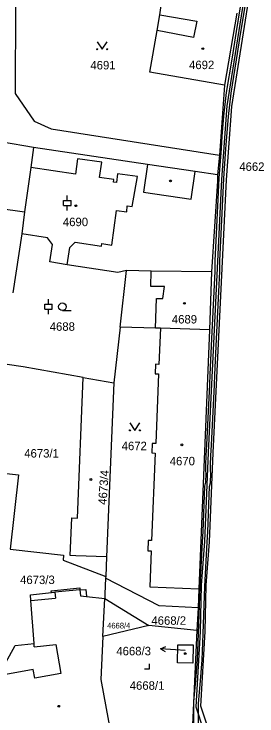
# Model space of a CAD drawing. Extents: x -756746 to -753363, y -1166406 to -1161727.
# Drawn here: x -755427.8 to -755379, y -1166083.9 to -1165943 of the extents above; entities that cross this region are included whole.
import ezdxf

# ---------------------------------------------------------------- set-up
doc = ezdxf.new("R2010")
doc.units = 0
for name, color, linetype in [('Hranice parcel', 7, 'Continuous'), ('Parcelní čísla', 7, 'Continuous'), ('Pop  PČ popisy', 7, 'Continuous'), ('Vnitřní kresba', 7, 'Continuous'), ('Věcná břemena k části', 7, 'Continuous'), ('Značky budov', 7, 'Continuous'), ('Značky kultur', 7, 'Continuous')]:
    doc.layers.add(name, color=color, linetype=linetype)

msp = doc.modelspace()

# ---------------------------------------------------------------- linework, layer by layer
at = {"layer": 'Hranice parcel'}
for p, q in [((-755383.06, -1165942.82), (-755385.55, -1165957.23)), ((-755385.55, -1165957.23), (-755386.57, -1165971.34)), ((-755423.88, -1165969.75), (-755430.07, -1165968.71)), ((-755386.57, -1165971.34), (-755386.95, -1165975.24)), ((-755425.63, -1165982.68), (-755426.22, -1165987.11)), ((-755426.22, -1165987.11), (-755428, -1165998.93)), ((-755406.47, -1166005.8), (-755405.17, -1165994.49)), ((-755388.17, -1165994.71), (-755388.54, -1166006.37)), ((-755406.47, -1166005.8), (-755407.75, -1166016.98)), ((-755388.54, -1166006.37), (-755398.39, -1166006.06)), ((-755388.54, -1166006.37), (-755390.72, -1166058.33)), ((-755413.89, -1166015.93), (-755407.75, -1166016.98)), ((-755407.75, -1166016.98), (-755409.19, -1166051.95)), ((-755409.19, -1166051.95), (-755409.37, -1166055.84)), ((-755409.37, -1166055.84), (-755409.38, -1166056.19)), ((-755390.72, -1166058.33), (-755390.85, -1166062.19)), ((-755413.21, -1166059.89), (-755409.57, -1166060.26)), ((-755409.94, -1166067.89), (-755409.57, -1166060.26)), ((-755409.57, -1166060.26), (-755400.71, -1166065.73)), ((-755390.85, -1166062.19), (-755391.06, -1166066.74)), ((-755400.71, -1166065.73), (-755409.94, -1166067.89)), ((-755391.06, -1166066.74), (-755400.71, -1166065.73)), ((-755391.06, -1166066.74), (-755392.01, -1166087.13))]:
    msp.add_line(p, q, dxfattribs=at)
for points in [[(-755426.57, -1165935.77), (-755427.46, -1165941.26), (-755427.51, -1165958.93), (-755423.7, -1165964.51), (-755420.3, -1165966.01), (-755386.57, -1165971.34)], [(-755385.55, -1165957.23), (-755400.55, -1165954.63), (-755399.02, -1165946.28), (-755398.52, -1165943.15), (-755398.08, -1165940.42)], [(-755423.88, -1165969.75), (-755424.42, -1165973.76), (-755425.63, -1165982.68)], [(-755386.95, -1165975.24), (-755391.4, -1165974.6), (-755401, -1165973.17), (-755423.88, -1165969.75)], [(-755386.95, -1165975.24), (-755386.95, -1165976.54), (-755388.17, -1165994.71)], [(-755460.03, -1165978.15), (-755458.54, -1165978.33), (-755440.43, -1165980.63), (-755425.63, -1165982.68)], [(-755405.17, -1165994.49), (-755406.91, -1165994.88), (-755417.08, -1165993.3), (-755420.56, -1165992.75), (-755420.01, -1165989.22), (-755421.05, -1165987.91), (-755426.22, -1165987.11)], [(-755388.17, -1165994.71), (-755400.27, -1165994.56), (-755405.17, -1165994.49)], [(-755398.39, -1166006.06), (-755399.35, -1166006.03), (-755406.47, -1166005.8)], [(-755398.39, -1166006.06), (-755398.69, -1166013.3), (-755399.39, -1166013.27), (-755399.47, -1166015.17), (-755398.77, -1166015.2), (-755399.34, -1166029.19), (-755400.03, -1166029.16), (-755400.11, -1166031.06), (-755399.42, -1166031.09), (-755400.15, -1166048.67), (-755400.85, -1166048.65), (-755400.93, -1166050.69), (-755400.23, -1166050.72), (-755400.53, -1166057.92), (-755390.72, -1166058.33)], [(-755413.89, -1166015.93), (-755425.95, -1166013.78), (-755429.15, -1166013.33)], [(-755409.19, -1166051.95), (-755415.36, -1166051.7), (-755416.5, -1166051.65), (-755416.19, -1166044.09), (-755415.05, -1166044.14), (-755413.89, -1166015.93)], [(-755431.68, -1166034.91), (-755426.85, -1166035.45), (-755428.52, -1166050.41)], [(-755428.52, -1166050.41), (-755417.85, -1166051.6), (-755417.89, -1166052.59), (-755409.37, -1166055.84)], [(-755409.38, -1166056.19), (-755409.53, -1166059.33), (-755409.57, -1166060.26)], [(-755390.85, -1166062.19), (-755398.64, -1166061.74), (-755409.38, -1166056.19)], [(-755430.92, -1166075.8), (-755427.55, -1166069.72), (-755423.74, -1166069.35), (-755424.37, -1166060.72), (-755424.46, -1166059.53), (-755420.25, -1166059.11), (-755420.29, -1166058.73), (-755414.57, -1166058.16), (-755414.53, -1166058.58), (-755413.34, -1166058.47), (-755413.21, -1166059.89)], [(-755409.94, -1166067.89), (-755410.35, -1166076.55), (-755407.85, -1166090.02)], [(-755391.8, -1166069.61), (-755391.86, -1166073.26), (-755394.95, -1166073.2), (-755394.93, -1166069.56), (-755391.8, -1166069.61)]]:
    msp.add_lwpolyline(points, dxfattribs=at)
at = {"layer": 'Pop  PČ popisy'}
for p, q in [((-755398.37, -1166070.37), (-755397.34, -1166069.94)), ((-755395.38, -1166070.58), (-755398.37, -1166070.37)), ((-755398.37, -1166070.37), (-755397.41, -1166070.94)), ((-755393.43, -1166070.73), (-755395.38, -1166070.58))]:
    msp.add_line(p, q, dxfattribs=at)
at = {"layer": 'Vnitřní kresba'}
for p, q in [((-755398.52, -1165943.15), (-755391.11, -1165944.41)), ((-755391.11, -1165944.41), (-755391.73, -1165947.67)), ((-755391.73, -1165947.67), (-755399.02, -1165946.28)), ((-755415.01, -1165972.02), (-755415.46, -1165975.09)), ((-755410.17, -1165972.74), (-755415.01, -1165972.02)), ((-755415.46, -1165975.09), (-755424.42, -1165973.76)), ((-755410.62, -1165975.8), (-755410.17, -1165972.74)), ((-755401, -1165973.17), (-755401.82, -1165978.71)), ((-755407.02, -1165975.06), (-755407.17, -1165976.81)), ((-755403.02, -1165975.59), (-755407.02, -1165975.06)), ((-755392.23, -1165980.14), (-755391.4, -1165974.6)), ((-755407.76, -1165976.22), (-755410.62, -1165975.8)), ((-755407.82, -1165976.72), (-755407.76, -1165976.22)), ((-755404.05, -1165981.6), (-755403.02, -1165975.59)), ((-755407.17, -1165976.81), (-755407.82, -1165976.72)), ((-755401.82, -1165978.71), (-755392.23, -1165980.14)), ((-755405.15, -1165982.71), (-755405.05, -1165981.46)), ((-755405.05, -1165981.46), (-755404.05, -1165981.6)), ((-755408.12, -1165989.38), (-755407.19, -1165982.44)), ((-755407.19, -1165982.44), (-755405.15, -1165982.71)), ((-755416.54, -1165989.87), (-755415.49, -1165988.76)), ((-755415.49, -1165988.76), (-755410.21, -1165989.57)), ((-755410.21, -1165989.57), (-755410.14, -1165989.07)), ((-755410.14, -1165989.07), (-755408.12, -1165989.38)), ((-755417.08, -1165993.3), (-755416.54, -1165989.87)), ((-755400.31, -1165997.66), (-755400.27, -1165994.56)), ((-755397.56, -1165997.69), (-755400.31, -1165997.66)), ((-755397.9, -1166000.1), (-755397.56, -1165997.69)), ((-755399.35, -1166006.03), (-755399.16, -1166000.06)), ((-755399.16, -1166000.06), (-755397.9, -1166000.1)), ((-755420.25, -1166059.11), (-755419.57, -1166059.04)), ((-755414.53, -1166058.58), (-755419.57, -1166059.04)), ((-755419.57, -1166059.04), (-755419.47, -1166060.24)), ((-755414.53, -1166058.58), (-755414.41, -1166059.77)), ((-755424.37, -1166060.72), (-755419.47, -1166060.24)), ((-755414.41, -1166059.77), (-755413.21, -1166059.89)), ((-755423.69, -1166069.96), (-755423.74, -1166069.35)), ((-755423.69, -1166069.96), (-755419.38, -1166069.53)), ((-755419.38, -1166069.53), (-755418.36, -1166075.36)), ((-755423.92, -1166074.54), (-755430.92, -1166075.8)), ((-755423.61, -1166076.29), (-755423.92, -1166074.54)), ((-755418.36, -1166075.36), (-755423.61, -1166076.29))]:
    msp.add_line(p, q, dxfattribs=at)
at = {"layer": 'Věcná břemena k části'}
for points in [[(-755385.7, -1165976), (-755385.24, -1165970.06), (-755385.09, -1165967.62), (-755384.74, -1165963.55), (-755384.22, -1165958.86), (-755383.1, -1165952.19), (-755382.24, -1165946.62), (-755380.28, -1165934.63), (-755379.25, -1165927.68), (-755378.78, -1165925.92), (-755378.82, -1165925), (-755376.67, -1165911.82), (-755376.32, -1165909.89), (-755375.93, -1165907.57), (-755373.96, -1165897.48), (-755373.19, -1165893.41), (-755373.15, -1165892.92), (-755371.85, -1165886.32), (-755371.15, -1165882.8), (-755369.79, -1165876), (-755369.69, -1165875.3), (-755368.15, -1165864.9), (-755367.31, -1165860.7)], [(-755373.13, -1165886.12), (-755385.09, -1165961.43), (-755386.11, -1165976.2), (-755388.84, -1166030.96), (-755389.57, -1166048.84), (-755390.21, -1166057.59), (-755390.43, -1166066.89), (-755391.29, -1166082.01), (-755389.73, -1166086.72), (-755384.8, -1166101.6), (-755324.15, -1166091.45)], [(-755324.31, -1166090.47), (-755384.12, -1166100.48), (-755388.74, -1166086.54), (-755390.29, -1166081.87), (-755389.43, -1166066.91), (-755389.21, -1166057.59), (-755388.57, -1166048.9), (-755387.84, -1166031.02), (-755385.11, -1165976.24), (-755384.09, -1165961.55), (-755372.14, -1165886.27)], [(-755381.26, -1165934.47), (-755383.22, -1165946.46), (-755384.08, -1165952.03), (-755385.2, -1165958.72), (-755385.74, -1165963.45), (-755386.09, -1165967.54), (-755386.24, -1165969.99), (-755386.7, -1165975.94), (-755387.24, -1165987.07), (-755387.45, -1165992.53), (-755387.49, -1165994.61), (-755387.62, -1165997.31), (-755388.12, -1166008.18), (-755388.51, -1166015.35), (-755388.55, -1166017.35), (-755389.17, -1166029.45), (-755389.29, -1166031.56), (-755389.32, -1166033.49), (-755389.35, -1166034.64), (-755389.25, -1166035.18), (-755389.38, -1166036.96), (-755389.54, -1166037.72), (-755389.89, -1166046.85), (-755390.04, -1166048.92), (-755390.49, -1166057.87), (-755390.83, -1166067.31), (-755391.04, -1166072.51), (-755391.36, -1166076.71), (-755391.73, -1166081.04), (-755391.75, -1166081.53), (-755391.74, -1166087.08)], [(-755390.73, -1166086.9), (-755390.75, -1166081.36), (-755390.36, -1166076.79), (-755390.04, -1166072.57), (-755389.83, -1166067.35), (-755389.49, -1166057.91), (-755389.04, -1166048.98), (-755388.89, -1166046.91), (-755388.54, -1166037.84), (-755388.38, -1166037.1), (-755388.25, -1166035.14), (-755388.35, -1166034.56), (-755388.32, -1166033.51), (-755388.29, -1166031.6), (-755388.17, -1166029.51), (-755387.55, -1166017.39), (-755387.51, -1166015.39), (-755387.12, -1166008.24), (-755386.62, -1165997.35), (-755386.49, -1165994.65), (-755386.45, -1165992.55), (-755386.24, -1165987.11), (-755385.7, -1165976)]]:
    msp.add_lwpolyline(points, dxfattribs=at)
at = {"layer": 'Značky budov'}
for centre in [(-755389.88, -1165949.94), (-755396.37, -1165976.47), (-755415.36, -1165981.46), (-755393.58, -1166001.05), (-755394.08, -1166029.45), (-755412.34, -1166036.4), (-755393.41, -1166071.34), (-755418.78, -1166081.91)]:
    msp.add_circle(centre, 0.175, dxfattribs=at)
at = {"layer": 'Značky kultur'}
for p, q in [((-755417.07, -1165980.39), (-755417.07, -1165979.39)), ((-755417.82, -1165980.39), (-755416.32, -1165980.39)), ((-755417.82, -1165981.39), (-755417.82, -1165980.39)), ((-755416.32, -1165981.39), (-755416.32, -1165980.39)), ((-755417.82, -1165981.39), (-755416.32, -1165981.39)), ((-755417.07, -1165982.39), (-755417.07, -1165981.39)), ((-755420.85, -1166001.24), (-755420.85, -1166000.24)), ((-755421.6, -1166001.24), (-755420.1, -1166001.24)), ((-755421.6, -1166002.24), (-755421.6, -1166001.24)), ((-755420.1, -1166002.24), (-755420.1, -1166001.24)), ((-755421.6, -1166002.24), (-755420.1, -1166002.24)), ((-755420.85, -1166003.24), (-755420.85, -1166002.24)), ((-755418.06, -1166002.48), (-755416.31, -1166002.48)), ((-755400.6, -1166074.38), (-755400.6, -1166073.38)), ((-755401.6, -1166074.38), (-755400.6, -1166074.38))]:
    msp.add_line(p, q, dxfattribs=at)
for points in [[(-755411.07, -1165948.56), (-755410.07, -1165950.06), (-755409.07, -1165948.56)], [(-755404.5, -1166025.04), (-755403.5, -1166026.54), (-755402.5, -1166025.04)]]:
    msp.add_lwpolyline(points, dxfattribs=at)
for centre, radius in [((-755411.07, -1165950.06), 0.1), ((-755409.07, -1165950.06), 0.1), ((-755418.06, -1166001.73), 0.75), ((-755404.5, -1166026.54), 0.1), ((-755402.5, -1166026.54), 0.1)]:
    msp.add_circle(centre, radius, dxfattribs=at)

# ---------------------------------------------------------------- texts
at = {"layer": 'Parcelní čísla'}
for s, height, p in [('4691', 1.7, (-755412.44, -1165954.1)), ('4692', 1.7, (-755392.65, -1165954.04)), ('4662', 1.7, (-755382.57, -1165974.46)), ('4690', 1.7, (-755417.96, -1165985.56)), ('4689', 1.7, (-755396.1, -1166005.09)), ('4688', 1.7, (-755420.6, -1166006.56)), ('4672', 1.7, (-755406.17, -1166030.52)), ('4673/1', 1.7, (-755425.71, -1166032)), ('4670', 1.7, (-755396.52, -1166033.56)), ('4673/3', 1.7, (-755426.54, -1166057.39)), ('4668/2', 1.7, (-755400.2, -1166065.56)), ('4668/4', 1.139, (-755409.08, -1166066.3)), ('4668/3', 1.7, (-755407.24, -1166071.69)), ('4668/1', 1.7, (-755404.55, -1166078.61))]:
    msp.add_text(s, height=height, dxfattribs=at).set_placement(p)
msp.add_text('4673/4', height=1.7, rotation=86, dxfattribs=at).set_placement((-755409.21, -1166041.52))

doc.saveas('drawing.dxf')
